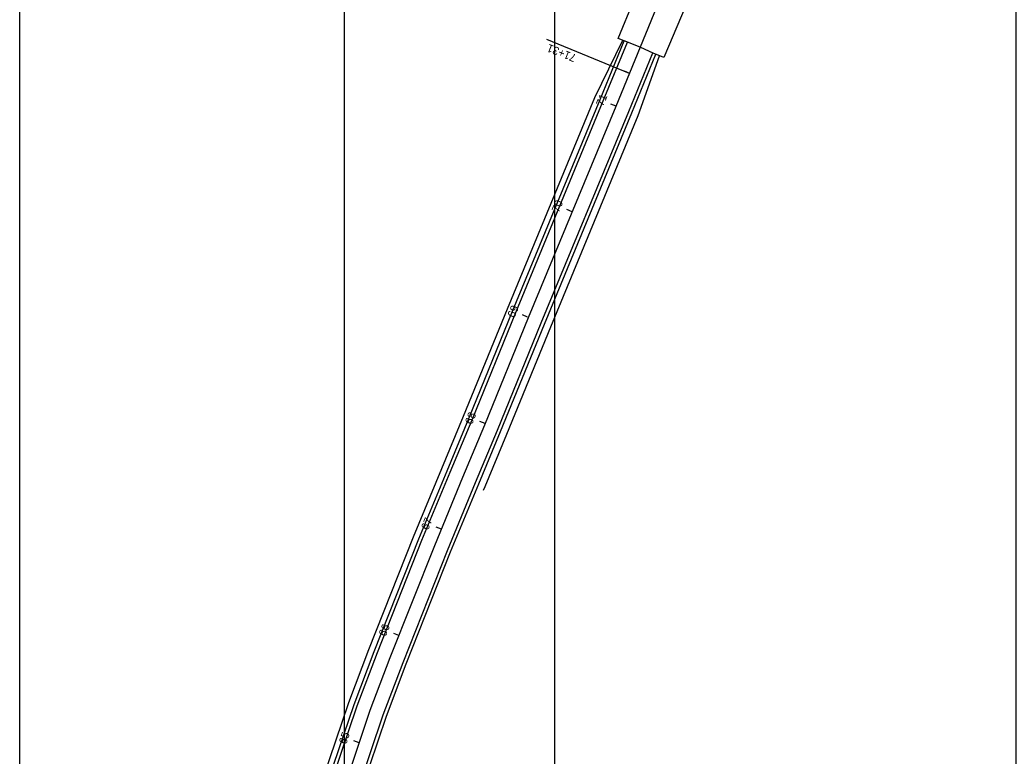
# Model space of a CAD drawing. Extents: x 2318076 to 2324211, y 613525 to 630327.
# Drawn here: x 2318413 to 2319284, y 621372 to 622015 of the extents above; entities that cross this region are included whole.
import ezdxf

# ---------------------------------------------------------------- set-up
doc = ezdxf.new("R2010")
doc.units = 0
for name, color, linetype in [('BR_X_Slab_Object', 7, 'Continuous'), ('GE_P_CL_50', 7, 'Continuous'), ('PV_P_EOP', 7, 'Continuous'), ('PV_P_Shoulder', 7, 'Continuous'), ('RD_X_GR_Lt', 7, 'Continuous'), ('RD_X_GR_Rt', 7, 'Continuous'), ('SC_Scratch3', 7, 'Continuous')]:
    doc.layers.add(name, color=color, linetype=linetype)

msp = doc.modelspace()

# ---------------------------------------------------------------- linework, layer by layer
at = {"layer": 'BR_X_Slab_Object'}
msp.add_lwpolyline([(2318975.86, 621982.32), (2318966.58, 621986.27), (2318955.8, 621991.11), (2318945.09, 621995.46), (2318936.06, 621999.02), (2318976.92, 622099.11), (2318986.65, 622094.78), (2318995.68, 622091.22), (2319006.8, 622086.52), (2319018.06, 622082.33), (2318975.86, 621982.32)], dxfattribs=at)
at = {"layer": 'GE_P_CL_50'}
for p, q in [((2318945.85, 621968.59), (2318873.7, 621998.24)), ((2318946.13, 621968.47), (2318941.52, 621970.41)), ((2318934.13, 621939.89), (2318929.52, 621941.82)), ((2318895.62, 621847.6), (2318891, 621849.52)), ((2318856.78, 621755.46), (2318852.18, 621757.42)), ((2318819.76, 621662.57), (2318815.11, 621664.39)), ((2318781.39, 621570.22), (2318776.78, 621572.14)), ((2318744.29, 621477.36), (2318739.64, 621479.2)), ((2318709.57, 621383.6), (2318704.84, 621385.2))]:
    msp.add_line(p, q, dxfattribs=at)
msp.add_lwpolyline([(2318697.08, 621346.57), (2318719.13, 621411.93), (2318736.61, 621457.99), (2318775.51, 621556.07), (2318800.25, 621615.57), (2318819.28, 621661.33), (2318857.56, 621755.12), (2318934.06, 621939.92), (2318972.07, 622032.4)], dxfattribs=at)
at = {"layer": 'PV_P_EOP'}
for points in [[(2318685.64, 621350.2), (2318707.83, 621415.98), (2318725.42, 621462.33), (2318764.39, 621560.59), (2318789.17, 621620.18), (2318808.18, 621665.9), (2318846.46, 621759.68), (2318922.97, 621944.49), (2318944.08, 621995.87)], [(2318708.52, 621342.94), (2318730.43, 621407.88), (2318747.8, 621453.65), (2318786.63, 621551.55), (2318811.33, 621610.96), (2318830.38, 621656.76), (2318868.66, 621750.56), (2318945.16, 621935.34), (2318966.16, 621986.46)]]:
    msp.add_lwpolyline(points, dxfattribs=at)
at = {"layer": 'PV_P_Shoulder'}
for points in [[(2318682.78, 621351.11), (2318705.01, 621416.99), (2318722.63, 621463.42), (2318761.61, 621561.71), (2318786.4, 621621.33), (2318805.41, 621667.04), (2318843.68, 621760.82), (2318920.2, 621945.64), (2318941.31, 621997.01)], [(2318711.38, 621342.03), (2318733.25, 621406.87), (2318750.59, 621452.56), (2318789.41, 621550.43), (2318814.1, 621609.81), (2318833.15, 621655.62), (2318871.43, 621749.42), (2318947.93, 621934.2), (2318968.94, 621985.32)]]:
    msp.add_lwpolyline(points, dxfattribs=at)
at = {"layer": 'RD_X_GR_Lt'}
msp.add_line((2318915.58, 621947.54), (2318940, 621997.47), dxfattribs=at)
msp.add_lwpolyline([(2318678.02, 621352.63), (2318700.3, 621418.68), (2318717.96, 621465.23), (2318756.98, 621563.6), (2318781.78, 621623.25), (2318800.79, 621668.95), (2318839.06, 621762.72), (2318915.58, 621947.54)], dxfattribs=at)
at = {"layer": 'RD_X_GR_Rt'}
msp.add_line((2318953.48, 621931.91), (2318972.19, 621983.88), dxfattribs=at)
msp.add_lwpolyline([(2318818.27, 621604.22), (2318819.64, 621607.51), (2318838.7, 621653.33), (2318876.98, 621747.14), (2318953.48, 621931.91)], dxfattribs=at)
at = {"layer": 'SC_Scratch3'}
for p, q in [((2318412.82, 614778.41), (2318412.82, 630327.22)), ((2318696.66, 614778.41), (2318696.66, 630327.22)), ((2318880.45, 614778.41), (2318880.45, 630327.22)), ((2319283.9, 614778.41), (2319283.9, 630327.22))]:
    msp.add_line(p, q, dxfattribs=at)

# ---------------------------------------------------------------- texts
at = {"layer": 'GE_P_CL_50'}
for s, rotation, p in [('71+31', 158.27955, (2318899.9, 621984.71)), ('71', 67.23321, (2318922.71, 621939.17)), ('70', 67.45942, (2318884.01, 621846.39)), ('69', 66.84295, (2318845.18, 621754.43)), ('68', 68.6645, (2318808.19, 621661.13)), ('67', 67.42254, (2318769.72, 621568.85)), ('66', 68.36598, (2318732.7, 621475.93)), ('65', 71.35754, (2318698.11, 621381.7))]:
    msp.add_text(s, height=7, rotation=rotation, dxfattribs=at).set_placement(p)

doc.saveas('drawing.dxf')
